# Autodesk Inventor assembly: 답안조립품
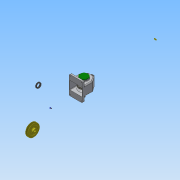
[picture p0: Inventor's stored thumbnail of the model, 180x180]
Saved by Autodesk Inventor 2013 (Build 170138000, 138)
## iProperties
Created: 2016-12
Part Number: 답안조립품
Document SubType Name: Assembly
Designer: Administrator
Author: Administrator
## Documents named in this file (15)
- C:\Users\Administrator\Desktop\461208V1008\답안조립품.iam
- C:\Users\Administrator\Desktop\461208V1008\키 - 6 x 6 x 22.ipt
- C:\Users\Administrator\Desktop\461208V1008\V-벨트풀리.ipt
- C:\Users\Administrator\Desktop\461208V1008\뒤커버.ipt
- C:\Users\Administrator\Desktop\461208V1008\멈춤나사 - M4x10.ipt
- C:\Users\Administrator\Desktop\461208V1008\베어링 6203.ipt
- C:\Users\Administrator\Desktop\461208V1008\볼트 M3 x 8.ipt
- C:\Users\Administrator\Desktop\461208V1008\볼트 M3 x 10.ipt
- C:\Users\Administrator\Desktop\461208V1008\부시.ipt
- C:\Users\Administrator\Desktop\461208V1008\부품1.ipt
- C:\Users\Administrator\Desktop\461208V1008\스퍼기어.ipt
- C:\Users\Administrator\Desktop\461208V1008\앞커버.ipt
- C:\Users\Administrator\Desktop\461208V1008\오일씰 28 40 8.ipt
- C:\Users\Administrator\Desktop\461208V1008\축.ipt
- C:\Users\Administrator\Desktop\461208V1008\키 - 5 x 5 x 18.ipt
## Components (9 placed, 3 different names)
1. V-벨트풀리:1
2. ISO 4762 M3 x 10:1
3. ISO 4762 M3 x 10:2
4. ISO 4762 M3 x 10:3
5. ISO 4762 M3 x 10:4
6. ISO 4762 M3 x 8:1
7. ISO 4762 M3 x 8:2
8. ISO 4762 M3 x 8:3
9. ISO 4762 M3 x 8:4
